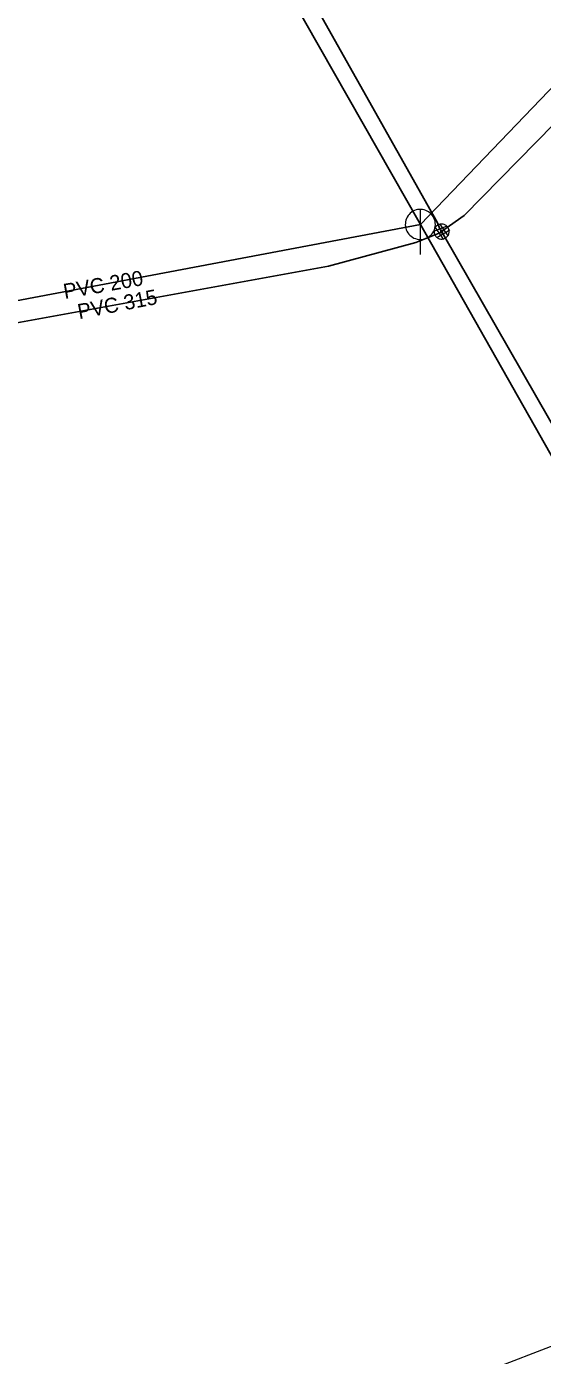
# Model space of a CAD drawing. Extents: x -807203 to -805207, y -993656 to -992505.
# Drawn here: x -806726 to -806691.7, y -993052.3 to -992964 of the extents above; entities that cross this region are included whole.
import ezdxf

# ---------------------------------------------------------------- set-up
doc = ezdxf.new("R2010")
doc.units = 0
doc.header["$LTSCALE"] = 0.4
for name, color, linetype, lineweight in [('1', 7, 'Continuous', 13), ('13', 7, 'Continuous', 13), ('14', 7, 'Continuous', 25), ('17', 7, 'Continuous', 25), ('22', 7, 'Continuous', 13), ('34', 7, 'Continuous', 13), ('47', 7, 'Continuous', 13)]:
    doc.layers.add(name, color=color, linetype=linetype, lineweight=lineweight)

msp = doc.modelspace()

# ---------------------------------------------------------------- linework, layer by layer
at = {"layer": '13'}
msp.add_lwpolyline([(-806684.207, -993048.995), (-806695.936, -993053.515), (-806704.138, -993057.129), (-806705.287, -993057.636), (-806704.804, -993061.366), (-806702.003, -993082.953)], dxfattribs=at)
at = {"layer": '14'}
for p, q in [((-806724.449, -992933.829), (-806699.85, -992977.12)), ((-806677.219, -992953.539), (-806699.85, -992977.12)), ((-806699.85, -992977.12), (-806674.969, -993021.039))]:
    msp.add_line(p, q, dxfattribs=at)
at = {"layer": '14', "lineweight": 13}
for q in [(-806698.289, -992977.488), (-806698.329, -992977.761)]:
    msp.add_line((-806698.437, -992977.594), q, dxfattribs=at)
at = {"layer": '14'}
msp.add_lwpolyline([(-807063.899, -993027.32), (-807029.679, -993022.599), (-806980.12, -993015.92), (-806932.19, -993009.809), (-806883.41, -993003.39), (-806833.609, -992997.23), (-806788.059, -992990.989), (-806765.85, -992988.129), (-806739.039, -992984.52), (-806699.85, -992977.12)], dxfattribs=at)
at = {"layer": '14', "lineweight": 13}
msp.add_lwpolyline([(-806698.599, -992977.709), (-806698.437, -992977.594), (-806698.548, -992977.42)], dxfattribs=at)
at = {"layer": '17'}
for points in [[(-806698.289, -992977.488), (-806696.94, -992976.539), (-806688.559, -992968), (-806676.219, -992954.809), (-806667.649, -992946.309), (-806638.16, -992917.219), (-806606.07, -992885.989)], [(-806698.548, -992977.42), (-806698.73, -992976.969), (-806725.329, -992929.699), (-806726.079, -992928.98), (-806742.265, -992900.26), (-806744.869, -992895.849)], [(-806733.749, -992984.949), (-806705.96, -992979.89), (-806700.149, -992978.32), (-806698.599, -992977.709)], [(-806698.329, -992977.761), (-806677.26, -993014.52), (-806673.778, -993020.307), (-806667.724, -993030.403), (-806667.65, -993030.526)]]:
    msp.add_lwpolyline(points, dxfattribs=at)
at = {"layer": '22'}
msp.add_line((-806699.85, -992979.12), (-806699.849, -992976.12), dxfattribs=at)
msp.add_lwpolyline([(-806698.85, -992977.12), (-806698.855, -992977.011), (-806698.873, -992976.903), (-806698.903, -992976.797), (-806698.943, -992976.696), (-806698.995, -992976.599), (-806699.057, -992976.509), (-806699.129, -992976.426), (-806699.209, -992976.352), (-806699.297, -992976.286), (-806699.391, -992976.231), (-806699.491, -992976.186), (-806699.596, -992976.153), (-806699.703, -992976.131), (-806699.812, -992976.121), (-806699.922, -992976.123), (-806700.03, -992976.137), (-806700.137, -992976.162), (-806700.24, -992976.199), (-806700.338, -992976.248), (-806700.43, -992976.306), (-806700.516, -992976.375), (-806700.593, -992976.452), (-806700.662, -992976.538), (-806700.721, -992976.63), (-806700.769, -992976.728), (-806700.806, -992976.831), (-806700.832, -992976.938), (-806700.846, -992977.046), (-806700.849, -992977.156), (-806700.839, -992977.265), (-806700.818, -992977.372), (-806700.784, -992977.476), (-806700.74, -992977.576), (-806700.685, -992977.671), (-806700.619, -992977.759), (-806700.545, -992977.839), (-806700.462, -992977.911), (-806700.372, -992977.973), (-806700.276, -992978.025), (-806700.174, -992978.066), (-806700.069, -992978.096), (-806699.961, -992978.114), (-806699.851, -992978.12), (-806699.742, -992978.114), (-806699.634, -992978.096), (-806699.529, -992978.067), (-806699.427, -992978.026), (-806699.33, -992977.974), (-806699.24, -992977.912), (-806699.157, -992977.841), (-806699.082, -992977.761), (-806699.017, -992977.673), (-806698.961, -992977.579), (-806698.917, -992977.479), (-806698.883, -992977.375), (-806698.861, -992977.267), (-806698.851, -992977.158)], close=True, dxfattribs=at)
at = {"layer": '34'}
for p, q in [((-806698.084, -992977.233), (-806699.012, -992977.605)), ((-806698.576, -992977.079), (-806698.001, -992977.897)), ((-806698.89, -992977.302), (-806698.308, -992978.115)), ((-806697.895, -992977.511), (-806698.763, -992978.009))]:
    msp.add_line(p, q, dxfattribs=at)
at = {"layer": '47'}
for points in [[(-806698.029, -992977.304), (-806698.061, -992977.263), (-806698.098, -992977.226), (-806698.138, -992977.193), (-806698.181, -992977.163), (-806698.228, -992977.139), (-806698.277, -992977.12), (-806698.327, -992977.106), (-806698.379, -992977.098), (-806698.431, -992977.094), (-806698.483, -992977.096), (-806698.536, -992977.103), (-806698.586, -992977.117), (-806698.635, -992977.135), (-806698.682, -992977.158), (-806698.726, -992977.186), (-806698.767, -992977.218), (-806698.804, -992977.255), (-806698.838, -992977.296), (-806698.867, -992977.338), (-806698.891, -992977.385), (-806698.91, -992977.434), (-806698.924, -992977.485), (-806698.933, -992977.537), (-806698.937, -992977.588), (-806698.934, -992977.64), (-806698.927, -992977.693), (-806698.914, -992977.744), (-806698.895, -992977.792), (-806698.872, -992977.839), (-806698.844, -992977.883), (-806698.812, -992977.924), (-806698.775, -992977.961), (-806698.735, -992977.995), (-806698.692, -992978.024), (-806698.645, -992978.048), (-806698.596, -992978.068), (-806698.546, -992978.082), (-806698.494, -992978.091), (-806698.442, -992978.094), (-806698.39, -992978.091), (-806698.337, -992978.084), (-806698.287, -992978.071), (-806698.238, -992978.052), (-806698.191, -992978.029), (-806698.147, -992978.001), (-806698.106, -992977.969), (-806698.069, -992977.932), (-806698.035, -992977.892), (-806698.006, -992977.849), (-806697.982, -992977.802), (-806697.962, -992977.753), (-806697.949, -992977.703), (-806697.94, -992977.652), (-806697.937, -992977.599), (-806697.939, -992977.547), (-806697.946, -992977.494), (-806697.959, -992977.445), (-806697.978, -992977.395), (-806698.001, -992977.348)], [(-806698.37, -992977.546), (-806698.375, -992977.539), (-806698.381, -992977.533), (-806698.387, -992977.528), (-806698.394, -992977.523), (-806698.402, -992977.519), (-806698.41, -992977.516), (-806698.419, -992977.513), (-806698.427, -992977.512), (-806698.436, -992977.512), (-806698.444, -992977.512), (-806698.453, -992977.513), (-806698.461, -992977.515), (-806698.469, -992977.518), (-806698.477, -992977.521), (-806698.484, -992977.527), (-806698.491, -992977.532), (-806698.497, -992977.538), (-806698.502, -992977.544), (-806698.507, -992977.551), (-806698.511, -992977.559), (-806698.514, -992977.567), (-806698.517, -992977.576), (-806698.518, -992977.584), (-806698.519, -992977.593), (-806698.518, -992977.601), (-806698.517, -992977.61), (-806698.515, -992977.618), (-806698.512, -992977.626), (-806698.509, -992977.634), (-806698.503, -992977.641), (-806698.498, -992977.648), (-806698.492, -992977.654), (-806698.486, -992977.659), (-806698.479, -992977.664), (-806698.471, -992977.668), (-806698.463, -992977.671), (-806698.454, -992977.674), (-806698.446, -992977.675), (-806698.437, -992977.676), (-806698.429, -992977.675), (-806698.42, -992977.674), (-806698.412, -992977.672), (-806698.404, -992977.669), (-806698.396, -992977.666), (-806698.389, -992977.66), (-806698.382, -992977.655), (-806698.376, -992977.649), (-806698.371, -992977.643), (-806698.366, -992977.636), (-806698.362, -992977.628), (-806698.359, -992977.62), (-806698.356, -992977.611), (-806698.355, -992977.603), (-806698.355, -992977.594), (-806698.355, -992977.586), (-806698.356, -992977.577), (-806698.358, -992977.569), (-806698.361, -992977.561), (-806698.364, -992977.553)]]:
    msp.add_lwpolyline(points, close=True, dxfattribs=at)

# ---------------------------------------------------------------- texts
at = {"layer": '1'}
for s, rotation, p in [('PVC 200 ', 10, (-806723.473, -992982.076)), ('PVC 315 ', 11, (-806722.515, -992983.419))]:
    msp.add_text(s, height=1, rotation=rotation, dxfattribs=at).set_placement(p)

doc.saveas('drawing.dxf')
